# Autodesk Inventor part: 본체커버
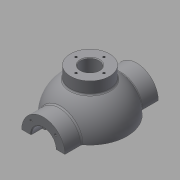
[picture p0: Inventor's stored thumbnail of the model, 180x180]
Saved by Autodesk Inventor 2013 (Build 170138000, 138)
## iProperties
Created: 2015-12
Part Number: 본체커버
Material: 일반
Document SubType Name: Modeling
Designer: mduedu
Density: 1 g/cm^3
Mass: 201.947 g
Surface Area: 428.16 cm^2
Volume: 201.947 cm^3
Author: mduedu
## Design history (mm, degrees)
sketch "스케치1"
  geometry: L1 (-53, 0)-(53, 0); A1 r 53 centre (0, 0) between (53, 0) and (-53, 0); 2 further points
  constraints: 2 coincident, 2 end point, 2 point on circle, 1 centre point, 1 horizontal, 1 midpoint
  dimensions: "d0" = 53 radius of A1
revolve "회전1" sketch "스케치1" stored, may be unused: angle "d2" = 90 deg
feature "쉘1" dims "d11" = 10
node "작업 평면1"
sketch "스케치2"
  geometry: C1 r 31 at (0, 0); 1 further point
  constraints: 1 centre point, 1 coincident
  dimensions: "d4" = 62 diameter of C1
extrude "돌출1" join sketch "스케치2" stored distance "d5" = 10; taper "d6" = 0 deg
hole "구멍1" diameter "d14" = 35; stored, may be unused: countersink angle "d18" = 90 deg, drill point angle "d20" = 0 deg; dims "d12" = 10, "d13" = 10, "d15" = 6, "d16" = 4, "d17" = 2, "d19" = 16
hole "구멍2" diameter "d23" = 27; stored, may be unused: countersink angle "d27" = 90 deg, drill point angle "d29" = 0 deg; dims "d21" = 10, "d22" = 10, "d24" = 6, "d25" = 4, "d26" = 2, "d28" = 16
fillet "모깎기1" dims "d30" = 0.3
chamfer "모따기1" distance "d40" = 1; stored, may be unused: second distance "d41" = 2, angle "d42" = 45 deg
sketch "스케치4"
  geometry: L1 (0, 0)-(0, -25); L2 (0, 0)-(-17.678, -17.678); A1 r 25 centre (0, 0) between (-17.678, -17.678) and (0, -25); 1 further point
  constraints: 4 end point, 2 point on circle, 1 centre point, 1 coincident, 1 vertical
  dimensions: "d43" = 50 diameter of A1; "d47" = 45 deg angle of L1 L2
hole "구멍4" sketch "스케치4" at (-17.678, -17.678) diameter "d49" = 3.242; stored, may be unused: countersink angle "d53" = 90 deg, drill point angle "d55" = 118 deg; dims "d50" = 11, "d51" = 4, "d52" = 2, "d54" = 13
node "작업 평면3"
sketch "스케치6"
  geometry: C1 r 65 at (0, 0); 1 further point
  constraints: 1 centre point, 1 coincident
  dimensions: "d78" = 130 diameter of C1
extrude "돌출3" join sketch "스케치6" distance "d80" = 10; taper "d81" = 0 deg
sketch "스케치7"
  geometry: C1 r 20 at (0, 0); 1 further point
  constraints: 1 centre point, 1 coincident
  dimensions: "d82" = 40 diameter of C1
extrude "돌출4" join sketch "스케치7" stored distance "d84" = 10; taper "d85" = 0 deg
sketch "스케치8"
  geometry: 2 further points
  constraints: 1 coincident
hole "구멍6" sketch "스케치8" at (0, 0) diameter "d86" = 20; stored, may be unused: countersink angle "d90" = 90 deg, drill point angle "d92" = 118 deg; dims "d87" = 7, "d88" = 40, "d89" = 5, "d91" = 10
fillet "모깎기2" dims "d93" = 0.3
sketch "스케치9"
  geometry: L1 (65, -75)-(-65, -75) reference; L2 (-45, -75)-(-38.245, -36.692); A1 r 53 centre (0, 0) between (42.988, 31) and (42.988, -31) reference; 1 further point
  constraints: 2 end point, 1 point on circle, 1 point on line
  dimensions: "d94" = 45 horizontal distance of L2.start point (0, 0); "d95" = 80 deg angle of L2 L1
feature "리브1" sketch "스케치9" dims "d96" = 1, "d97" = 8, "d98" = 0, "d99" = 0, "d100" = 1, "d101" = 1
sketch "스케치10"
  geometry: L1 (0, 0)-(0, -55); L2 (0, 0)-(-38.891, -38.891); A1 r 55 centre (0, 0) between (0, -55) and (-38.891, -38.891); 2 further points
  constraints: 4 end point, 2 coincident, 2 point on circle, 1 centre point, 1 vertical
  dimensions: "d105" = 110 diameter of A1; "d107" = 45 deg angle of L1 L2
hole "구멍7" sketch "스케치10" at (-38.891, -38.891) diameter "d109" = 10; stored, may be unused: countersink angle "d113" = 90 deg, drill point angle "d115" = 118 deg; dims "d110" = 7, "d111" = 40, "d112" = 5, "d114" = 10
fillet "모깎기3" dims "d120" = 3
fillet "모깎기4" dims "d121" = 3, "d122" = 3
fillet "모깎기5" dims "d123" = 3
fillet "모깎기6" dims "d124" = 3
sketch "스케치11"
  geometry: C1 r 5 at (-38.891, 38.891) reference; C2 r 5 at (38.891, 38.891) reference; C3 r 5 at (38.891, -38.891) reference; C4 r 5 at (-38.891, -38.891) reference; C5 r 20 at (0, 0) reference; C6 r 65 at (0, 0) reference; 1 further point
  constraints: 3 other
feature "엠보싱1" sketch "스케치11" dims "d125" = 0.5, "d126" = 0
sketch "스케치12"
  geometry: L1 (0, 100)-(0, -100); L2 (0, 100)-(-150, 100); L3 (-150, 100)-(-150, -100); L4 (-150, -100)-(0, -100); 2 further points
  constraints: 8 end point, 3 perpendicular, 1 coincident, 1 midpoint, 1 vertical
  dimensions: "d127" = 200 distance of L2.end L3.end; "d129" = 150 distance of L3.end L1.end
extrude "돌출5" cut sketch "스케치12" stored distance "d130" = 10; taper "d131" = 0 deg
node "작업 평면4"
sketch "스케치16"
  geometry: C1 r 28 at (0, 0); 1 further point
  constraints: 1 centre point, 1 coincident
  dimensions: "d148" = 56 diameter of C1
extrude "돌출9" join sketch "스케치16" stored distance "d150" = 5; taper "d151" = 0 deg
hole "구멍8" diameter "d154" = 26; stored, may be unused: countersink angle "d158" = 90 deg, drill point angle "d160" = 118 deg; dims "d152" = 10, "d153" = 10, "d155" = 6, "d156" = 4, "d157" = 2, "d159" = 8
sketch "스케치17" dims "d161" = 40
  geometry: 3 further points
  constraints: 2 vertical alignment, 1 coincident, 2 other
hole "구멍9" sketch "스케치17" at (0, 20) diameter "d163" = 3.242; stored, may be unused: countersink angle "d167" = 90 deg, drill point angle "d169" = 118 deg; dims "d164" = 8, "d165" = 4, "d166" = 2, "d168" = 10
fillet "모깎기11" dims "d173" = 3
chamfer "모따기2" distance "d174" = 1; stored, may be unused: second distance "d175" = 2, angle "d176" = 45 deg
node "솔리드1"
mirror "대칭1"
mirror "대칭2"
pattern_circular "원형 패턴1" dims angle "d57" = 360 deg
mirror "대칭3"
pattern_circular "원형 패턴3" dims angle "d103" = 360 deg
pattern_circular "원형 패턴4" dims "d40" = 1, angle "d118" = 360 deg
pattern_circular "원형 패턴5" dims angle "d171" = 360 deg
node "투영된 루프1"
other parameters: "d3" = 67, "d77" = -85, "d147" = 62
